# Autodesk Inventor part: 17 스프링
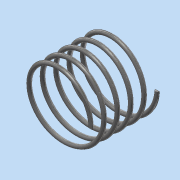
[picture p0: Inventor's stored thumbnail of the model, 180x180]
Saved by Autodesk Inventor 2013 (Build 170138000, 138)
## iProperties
Created: 2016-06
Part Number: 17 스프링
Material: 강철, 탄소
Document SubType Name: Modeling
Designer: Administrator
Density: 7.87 g/cm^3
Mass: 1.62548 g
Surface Area: 8.36348 cm^2
Volume: 0.206541 cm^3
Author: Administrator
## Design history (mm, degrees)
sketch "스케치1"
  geometry: L1 (0, 0)-(8.5, 0); L2 (8.5, 0)-(8.5, 16.67); L3 (8.5, 16.67)-(0, 16.67); L4 (0, 16.67)-(0, 0); C1 r 0.5 at (8.5, 0)
  constraints: 8 end point, 2 parallel, 1 centre point, 1 coincident, 1 horizontal, 1 perpendicular
  dimensions: "d0" = 16.66987 distance of L3.end L1.start (derived); "d1" = 1 diameter of C1; "d2" = 17 diameter of L2 L4
feature "코일1" sketch "스케치1" pitch "d3" = 10; turns "d5" = 5; dims "d4" = 16.66987 (= d0), "d6" = 0, angle "d7" = 90 deg, angle "d8" = 90 deg, "d9" = 0, "d10" = 0
sketch "스케치2"
  geometry: L1 (0, 15)-(16.67, 15); L2 (16.67, 15)-(16.67, -15); L3 (16.67, -15)-(0, -15); L4 (0, -15)-(0, 15); 4 further points
  constraints: 8 end point, 2 coincident, 2 midpoint, 2 parallel, 1 horizontal, 1 perpendicular
  dimensions: "d11" = 30 distance of L1.end L2.end
extrude "돌출1" sketch "스케치2" stored distance "d13" = 50; taper "d14" = 0 deg
node "솔리드1"
